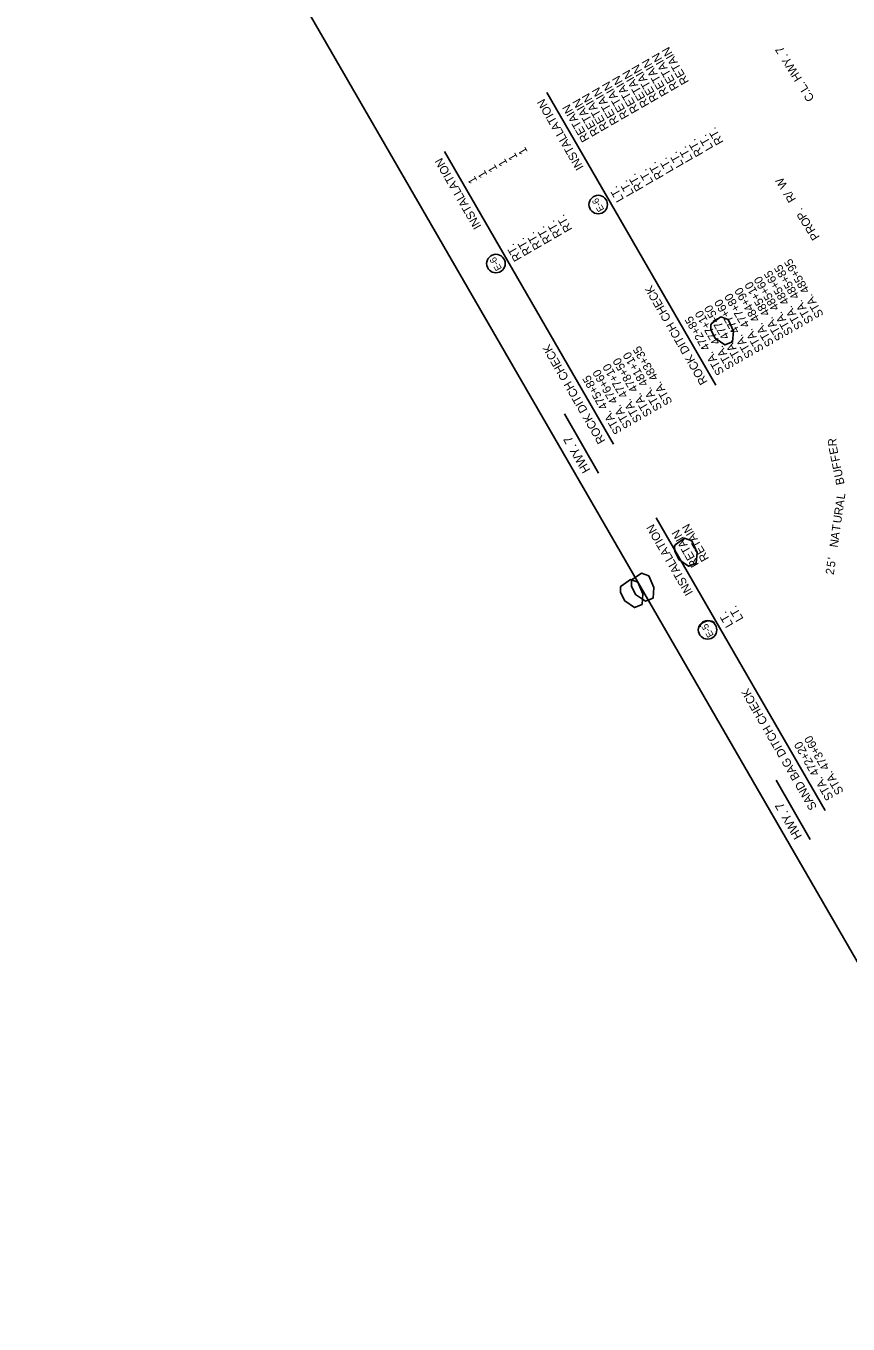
# Model space of a CAD drawing. Extents: x 956270 to 957915, y 1920230 to 1922423.
# Drawn here: x 956270 to 956857, y 1920520 to 1921447 of the extents above; entities that cross this region are included whole.
import ezdxf

# ---------------------------------------------------------------- set-up
doc = ezdxf.new("R2010")
doc.units = 0
for name, color, linetype in [('1', 7, 'Continuous'), ('44', 7, 'Continuous'), ('NO PLOT', 7, 'Continuous'), ('R_Draft', 7, 'Continuous'), ('S_TREE', 7, 'Continuous')]:
    doc.layers.add(name, color=color, linetype=linetype)

msp = doc.modelspace()

# ---------------------------------------------------------------- linework, layer by layer
at = {"layer": '1'}
for centre in [(956678.4, 1921319.47), (956605.44, 1921277.35), (956756.39, 1921015.9)]:
    msp.add_circle(centre, 6.61, dxfattribs=at)
at = {"layer": '44'}
for p, q in [((956762.28, 1921190.65), (956641.78, 1921399.37)), ((956689.32, 1921148.52), (956568.81, 1921357.24)), ((956678.69, 1921127.74), (956654.27, 1921170.04)), ((956678.69, 1921127.74), (956654.27, 1921170.04)), ((956840.26, 1920887.08), (956719.76, 1921095.8)), ((956829.64, 1920866.3), (956805.22, 1920908.59))]:
    msp.add_line(p, q, dxfattribs=at)
at = {"layer": 'NO PLOT'}
msp.add_lwpolyline([(957012.51, 1920520.44), (956420.48, 1921545.87), (956463.26, 1921570.57), (956365.36, 1921740.14), (956378, 1921747.44), (956270.25, 1921934.07), (956666.17, 1922162.65), (956816.66, 1921901.98), (956749.98, 1921863.48), (956962.48, 1921495.42), (957029.16, 1921533.92), (957172.25, 1921286.08), (957120.9, 1921256.43), (957292.23, 1920959.68), (957343.58, 1920989.33), (957463.85, 1920781.02)], close=True, dxfattribs=at)
msp.add_lwpolyline([(957012.51, 1920520.44), (956420.48, 1921545.87), (956463.26, 1921570.57), (956365.36, 1921740.14), (956378, 1921747.44), (956270.25, 1921934.07), (956666.17, 1922162.65), (956816.66, 1921901.98), (956749.98, 1921863.48), (956962.48, 1921495.42), (957029.16, 1921533.92), (957172.25, 1921286.08), (957120.9, 1921256.43), (957292.23, 1920959.68), (957343.58, 1920989.33), (957463.85, 1920781.02)], close=True, dxfattribs=at)
msp.add_lwpolyline([(957012.51, 1920520.44), (956420.48, 1921545.87), (956463.26, 1921570.57), (956365.36, 1921740.14), (956378, 1921747.44), (956270.25, 1921934.07), (956666.17, 1922162.65), (956816.66, 1921901.98), (956749.98, 1921863.48), (956962.48, 1921495.42), (957029.16, 1921533.92), (957172.25, 1921286.08), (957120.9, 1921256.43), (957292.23, 1920959.68), (957343.58, 1920989.33), (957463.85, 1920781.02)], close=True, dxfattribs=at)
msp.add_lwpolyline([(957012.51, 1920520.44), (956420.48, 1921545.87), (956463.26, 1921570.57), (956365.36, 1921740.14), (956378, 1921747.44), (956270.25, 1921934.07), (956666.17, 1922162.65), (956816.66, 1921901.98), (956749.98, 1921863.48), (956962.48, 1921495.42), (957029.16, 1921533.92), (957172.25, 1921286.08), (957120.9, 1921256.43), (957292.23, 1920959.68), (957343.58, 1920989.33), (957463.85, 1920781.02)], close=True, dxfattribs=at)
msp.add_lwpolyline([(957012.51, 1920520.44), (956420.48, 1921545.87), (956463.26, 1921570.57), (956365.36, 1921740.14), (956378, 1921747.44), (956270.25, 1921934.07), (956666.17, 1922162.65), (956816.66, 1921901.98), (956749.98, 1921863.48), (956962.48, 1921495.42), (957029.16, 1921533.92), (957172.25, 1921286.08), (957120.9, 1921256.43), (957292.23, 1920959.68), (957343.58, 1920989.33), (957463.85, 1920781.02)], close=True, dxfattribs=at)
at = {"layer": 'S_TREE'}
for points in [[(956759.15, 1921234.57), (956765.91, 1921239.3), (956771.14, 1921237.44), (956774.79, 1921229.12), (956774.16, 1921221.52), (956768.77, 1921219.27), (956761.76, 1921224.01), (956758.81, 1921230.04), (956758.78, 1921233.74), (956759.74, 1921235.15)], [(956733.26, 1921076.58), (956740.02, 1921081.31), (956745.25, 1921079.45), (956748.9, 1921071.13), (956748.27, 1921063.53), (956742.88, 1921061.28), (956735.87, 1921066.02), (956732.92, 1921072.05), (956732.89, 1921075.75), (956733.85, 1921077.16)], [(956694.68, 1921047.13), (956701.43, 1921051.86), (956706.66, 1921050.01), (956710.31, 1921041.69), (956709.69, 1921034.08), (956704.29, 1921031.84), (956697.28, 1921036.58), (956694.33, 1921042.6), (956694.3, 1921046.31), (956695.27, 1921047.72)], [(956702.47, 1921051.63), (956709.22, 1921056.36), (956714.46, 1921054.51), (956718.11, 1921046.19), (956717.48, 1921038.58), (956712.09, 1921036.34), (956705.08, 1921041.08), (956702.13, 1921047.1), (956702.1, 1921050.81), (956703.06, 1921052.22)]]:
    msp.add_lwpolyline(points, dxfattribs=at)
msp.add_ellipse((956756.24, 1921019.26), major_axis=(-5.2, -1.23), ratio=0.540699, start_param=3.141593, end_param=6.283185, dxfattribs=at)

# ---------------------------------------------------------------- texts
at = {"layer": '1'}
for s, p in [('E-6 ', (956682.81, 1921316.01)), ('E-6 ', (956609.85, 1921273.89)), ('E-5 ', (956760.94, 1921012.18))]:
    msp.add_text(s, height=4.8, rotation=120, dxfattribs=at).set_placement(p)
at = {"layer": '44'}
for s, height, p in [('RETAIN', 6, (956743.3, 1921407.12)), ('RETAIN', 6, (956728.9, 1921398.81)), ('RETAIN', 6, (956736.12, 1921402.97)), ('RETAIN', 6, (956715.09, 1921390.83)), ('RETAIN', 6, (956721.69, 1921394.64)), ('RETAIN', 6, (956700.66, 1921382.5)), ('RETAIN', 6, (956707.84, 1921386.64)), ('INSTALLATION', 6, (956668.2, 1921346.08)), ('RETAIN', 6, (956679.62, 1921370.35)), ('RETAIN', 6, (956686.22, 1921374.16)), ('RETAIN', 6, (956693.44, 1921378.33)), ('RETAIN', 6, (956672.41, 1921366.19)), ('LT.', 6, (956760.7, 1921360.06)), ('RT.', 6, (956767.99, 1921364.11)), ('1', 6, (956628.29, 1921357.17)), ('LT.', 6, (956746.27, 1921351.73)), ('RT.', 6, (956753.56, 1921355.77)), ('INSTALLATION', 6, (956595.24, 1921303.96)), ('1', 6, (956606.68, 1921344.69)), ('1', 6, (956613.9, 1921348.85)), ('1', 6, (956621.11, 1921353.02)), ('RT.', 6, (956725.31, 1921339.46)), ('LT.', 6, (956732.45, 1921343.75)), ('LT.', 6, (956739.67, 1921347.92)), ('1', 6, (956592.32, 1921336.4)), ('1', 6, (956599.5, 1921340.54)), ('RT.', 6, (956710.88, 1921331.13)), ('LT.', 6, (956718.02, 1921335.42)), ('LT.', 6, (956696.99, 1921323.28)), ('LT.', 6, (956704.2, 1921327.44)), ('RT.', 6, (956660.1, 1921301.82)), ('RT.', 6, (956645.67, 1921293.49)), ('RT.', 6, (956652.89, 1921297.65)), ('RT.', 6, (956631.28, 1921285.18)), ('RT.', 6, (956638.46, 1921289.32)), ('RT.', 6, (956624.09, 1921281.03)), ('STA. 485+85', 6, (956832.18, 1921236.54)), ('STA. 485+95', 6, (956839.4, 1921240.71)), ('STA. 485+60', 6, (956817.75, 1921228.21)), ('STA. 485+65', 6, (956824.97, 1921232.38)), ('ROCK DITCH CHECK', 6, (956756.63, 1921192.92)), ('STA. 477+80', 6, (956796.72, 1921216.07)), ('STA. 484+90', 6, (956803.94, 1921220.23)), ('STA. 485+10', 6, (956811.15, 1921224.4)), ('STA. 477+50', 6, (956782.29, 1921207.74)), ('STA. 477+60', 6, (956789.5, 1921211.9)), ('STA. 472+85', 6, (956768.47, 1921199.76)), ('STA. 477+10', 6, (956775.69, 1921203.92)), ('ROCK DITCH CHECK', 6, (956683.67, 1921150.8)), ('STA. 478+50', 6, (956717.08, 1921170.09)), ('STA. 481+10', 6, (956724.3, 1921174.26)), ('STA. 483+35', 6, (956731.52, 1921178.42)), ('STA. 476+60', 6, (956702.69, 1921161.78)), ('STA. 477+10', 6, (956709.87, 1921165.93)), ('STA. 475+85', 6, (956695.51, 1921157.63)), ('HWY. 7', 6.25, (956672.99, 1921130.05)), ('HWY. 7', 6.25, (956672.99, 1921130.05)), ('INSTALLATION', 6, (956746.19, 1921042.51)), ('RETAIN', 6, (956757.61, 1921066.78)), ('RETAIN', 6, (956750.39, 1921062.61)), ('LT.', 6, (956782.19, 1921023.87)), ('LT.', 6, (956774.97, 1921019.71)), ('SAND BAG DITCH CHECK', 6, (956834.61, 1920889.35)), ('STA. 472+20', 6, (956846.45, 1920896.19)), ('STA. 473+60', 6, (956853.67, 1920900.35)), ('HWY. 7', 6.25, (956823.94, 1920868.6))]:
    msp.add_text(s, height=height, rotation=120, dxfattribs=at).set_placement(p)
at = {"layer": 'R_Draft'}
for s, rotation, p in [('C.L. HWY. 7', 121.71363, (956832.82, 1921395.21)), ('W', 122.05288, (956813.6, 1921333.05)), ('/', 122.05288, (956816.71, 1921328.09)), ('R', 122.05288, (956819.72, 1921323.28)), ('P', 122.05288, (956827.46, 1921310.91)), ('.', 122.05288, (956824.46, 1921315.71)), ('O', 122.05288, (956830.57, 1921305.94)), ('R', 122.05288, (956833.58, 1921301.14)), ('P', 122.05288, (956836.59, 1921296.33)), ('R', 92.10778, (956848.49, 1921147.03)), ('E', 101.55546, (956849.68, 1921141.77)), ('F', 101.55546, (956850.76, 1921136.49)), ('F', 101.55546, (956851.84, 1921131.22)), ('U', 101.55546, (956852.99, 1921125.57)), ('B', 101.55546, (956854.13, 1921120.02)), ('A', 81.81509, (956853.27, 1921102.99)), ('L', 81.81509, (956854.11, 1921108.79)), ('R', 81.81509, (956852.46, 1921097.38)), ('T', 81.81509, (956850.81, 1921085.88)), ('U', 81.81509, (956851.64, 1921091.68)), ('N', 81.81509, (956849.17, 1921074.47)), ('A', 81.81509, (956849.98, 1921080.08)), ('5', 81.81509, (956847.13, 1921060.3)), ("'", 81.81509, (956847.9, 1921065.63)), ('2', 81.81509, (956846.36, 1921054.97))]:
    msp.add_text(s, height=6, rotation=rotation, dxfattribs=at).set_placement(p)

doc.saveas('drawing.dxf')
